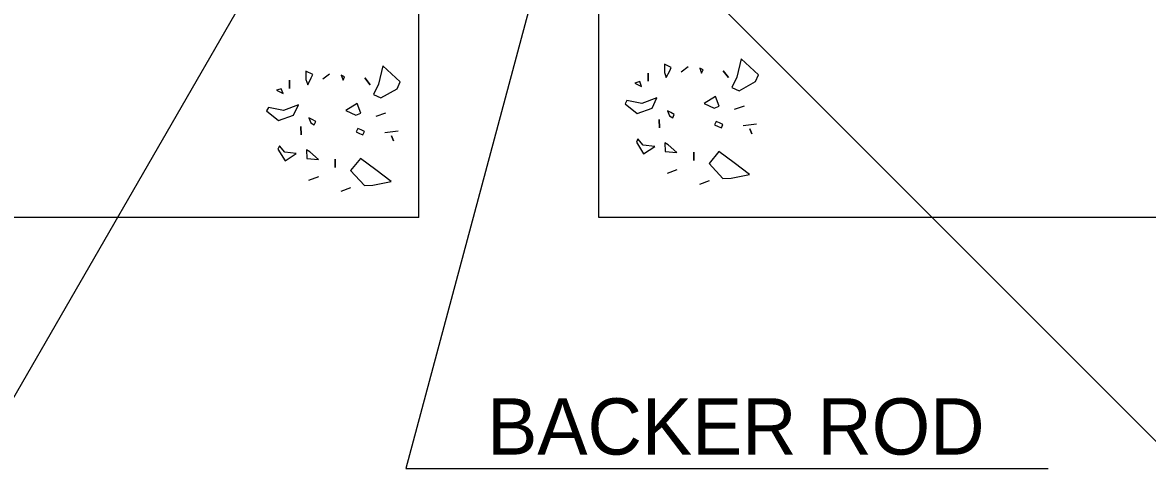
# Model space of a CAD drawing. Extents: x 0 to 11.3, y 0 to 7.8.
# Drawn here: x 2.89 to 3.931, y 1.625 to 2.037 of the extents above; entities that cross this region are included whole.
import ezdxf

# ---------------------------------------------------------------- set-up
doc = ezdxf.new("R2010")
doc.units = 0
for name, color, linetype in [('BRDG_ANNO_General-Notes', 7, 'Continuous'), ('BRDG_BASE_Obj-Line', 7, 'Continuous'), ('BRDG_BASE_Pattern', 7, 'Continuous')]:
    doc.layers.add(name, color=color, linetype=linetype)

msp = doc.modelspace()

# ---------------------------------------------------------------- linework, layer by layer
at = {"layer": 'BRDG_ANNO_General-Notes'}
for p, q in [((3.2567, 2.3401), (2.8525, 1.6399)), ((3.3467, 2.2423), (3.9645, 1.6245)), ((3.372, 2.0994), (3.2448, 1.6246)), ((3.2448, 1.6246), (3.8396, 1.6246))]:
    msp.add_line(p, q, dxfattribs=at)
at = {"layer": 'BRDG_BASE_Obj-Line'}
for p, q in [((3.2567, 1.857), (3.2567, 2.3987)), ((3.4234, 1.857), (3.4234, 2.3987)), ((3.2567, 1.857), (2.122, 1.857)), ((4.5581, 1.857), (3.4234, 1.857))]:
    msp.add_line(p, q, dxfattribs=at)
at = {"layer": 'BRDG_BASE_Pattern'}
for p, q in [((3.168, 1.9851), (3.1742, 1.9899)), ((3.4998, 1.9916), (3.5061, 1.9965)), ((3.5492, 1.9572), (3.5582, 1.9603)), ((3.2173, 1.9507), (3.2263, 1.9538)), ((3.5571, 1.9419), (3.5696, 1.9436)), ((3.2253, 1.9354), (3.2378, 1.9371)), ((3.487, 1.8978), (3.496, 1.9013)), ((3.1551, 1.8913), (3.1642, 1.8948)), ((3.5169, 1.8878), (3.5259, 1.8912)), ((3.185, 1.8812), (3.194, 1.8847))]:
    msp.add_line(p, q, dxfattribs=at)
for points in [[(3.5513, 1.9867), (3.5467, 1.9773), (3.5533, 1.9742), (3.5686, 1.9826), (3.5714, 1.9888), (3.5554, 2.0038)], [(3.1523, 1.9847), (3.1541, 1.9798), (3.1572, 1.9861), (3.1586, 1.9892), (3.1523, 1.9923)], [(3.2194, 1.9802), (3.2148, 1.9708), (3.2215, 1.9677), (3.2367, 1.976), (3.2395, 1.9823), (3.2235, 1.9972)], [(3.469, 1.9829), (3.469, 1.9905)], [(3.4842, 1.9912), (3.4859, 1.9864), (3.4891, 1.9926), (3.4905, 1.9957), (3.4842, 1.9989)], [(3.5169, 1.9951), (3.5186, 1.9905), (3.52, 1.9936), (3.52, 1.9936), (3.52, 1.9936), (3.52, 1.9936), (3.5169, 1.9951), (3.5169, 1.9951)], [(3.5436, 1.9864), (3.5387, 1.9926)], [(3.1371, 1.9764), (3.1371, 1.984)], [(3.185, 1.9885), (3.1867, 1.984), (3.1881, 1.9871), (3.1881, 1.9871), (3.1881, 1.9871), (3.1881, 1.9871), (3.185, 1.9885), (3.185, 1.9885)], [(3.2117, 1.9798), (3.2069, 1.9861)], [(3.4568, 1.9811), (3.463, 1.978), (3.4613, 1.9826)], [(3.1249, 1.9746), (3.1311, 1.9715), (3.1294, 1.976)], [(3.521, 1.9624), (3.5304, 1.9582), (3.5349, 1.96), (3.5315, 1.969)], [(3.1159, 1.9556), (3.127, 1.9465), (3.1409, 1.9517), (3.1454, 1.9611), (3.1315, 1.9559), (3.1176, 1.9587)], [(3.1892, 1.9559), (3.1985, 1.9517), (3.203, 1.9535), (3.1996, 1.9625)], [(3.4478, 1.9621), (3.4589, 1.953), (3.4728, 1.9582), (3.4773, 1.9676), (3.4634, 1.9624), (3.4495, 1.9652)], [(3.1569, 1.9444), (3.16, 1.9427), (3.16, 1.9427), (3.1614, 1.9458), (3.1614, 1.9458), (3.1582, 1.9476), (3.1582, 1.9476), (3.1551, 1.949), (3.1551, 1.949), (3.1569, 1.9444)], [(3.4888, 1.9509), (3.4919, 1.9492), (3.4919, 1.9492), (3.4932, 1.9523), (3.4932, 1.9523), (3.4901, 1.9541), (3.4901, 1.9541), (3.487, 1.9555), (3.487, 1.9555), (3.4888, 1.9509)], [(3.1478, 1.9333), (3.1475, 1.941)], [(3.202, 1.9347), (3.2051, 1.9333), (3.2065, 1.9365), (3.2065, 1.9365), (3.2034, 1.9379), (3.2034, 1.9379), (3.2003, 1.9392), (3.2003, 1.9392), (3.2003, 1.9392), (3.1989, 1.9361)], [(3.4797, 1.9398), (3.4794, 1.9475)], [(3.5339, 1.9412), (3.537, 1.9398), (3.5384, 1.943), (3.5384, 1.943), (3.5353, 1.9444), (3.5353, 1.9444), (3.5321, 1.9457), (3.5321, 1.9457), (3.5321, 1.9457), (3.5307, 1.9426)], [(3.5651, 1.9343), (3.5634, 1.9388)], [(3.2332, 1.9278), (3.2315, 1.9323)], [(3.4582, 1.9267), (3.4648, 1.9159), (3.4752, 1.9225), (3.4644, 1.9239), (3.4596, 1.9298)], [(3.1263, 1.9202), (3.1329, 1.9094), (3.1433, 1.916), (3.1326, 1.9173), (3.1277, 1.9233)], [(3.153, 1.9115), (3.1638, 1.9104), (3.1638, 1.9104), (3.1558, 1.9177), (3.1527, 1.9194)], [(3.4849, 1.918), (3.4957, 1.9169), (3.4957, 1.9169), (3.4877, 1.9242), (3.4846, 1.9259)], [(3.5113, 1.9096), (3.5113, 1.9173)], [(3.5255, 1.9069), (3.5384, 1.893), (3.546, 1.8933), (3.563, 1.8968), (3.5488, 1.9076), (3.5346, 1.918)], [(3.1794, 1.9031), (3.1794, 1.9108)], [(3.1936, 1.9004), (3.2065, 1.8865), (3.2142, 1.8868), (3.2311, 1.8903), (3.2169, 1.901), (3.2027, 1.9115)]]:
    msp.add_lwpolyline(points, close=True, dxfattribs=at)

# ---------------------------------------------------------------- texts
at = {"layer": 'BRDG_ANNO_General-Notes'}
msp.add_text('BACKER ROD', height=0.05208, dxfattribs=at).set_placement((3.3201, 1.6374))

doc.saveas('drawing.dxf')
